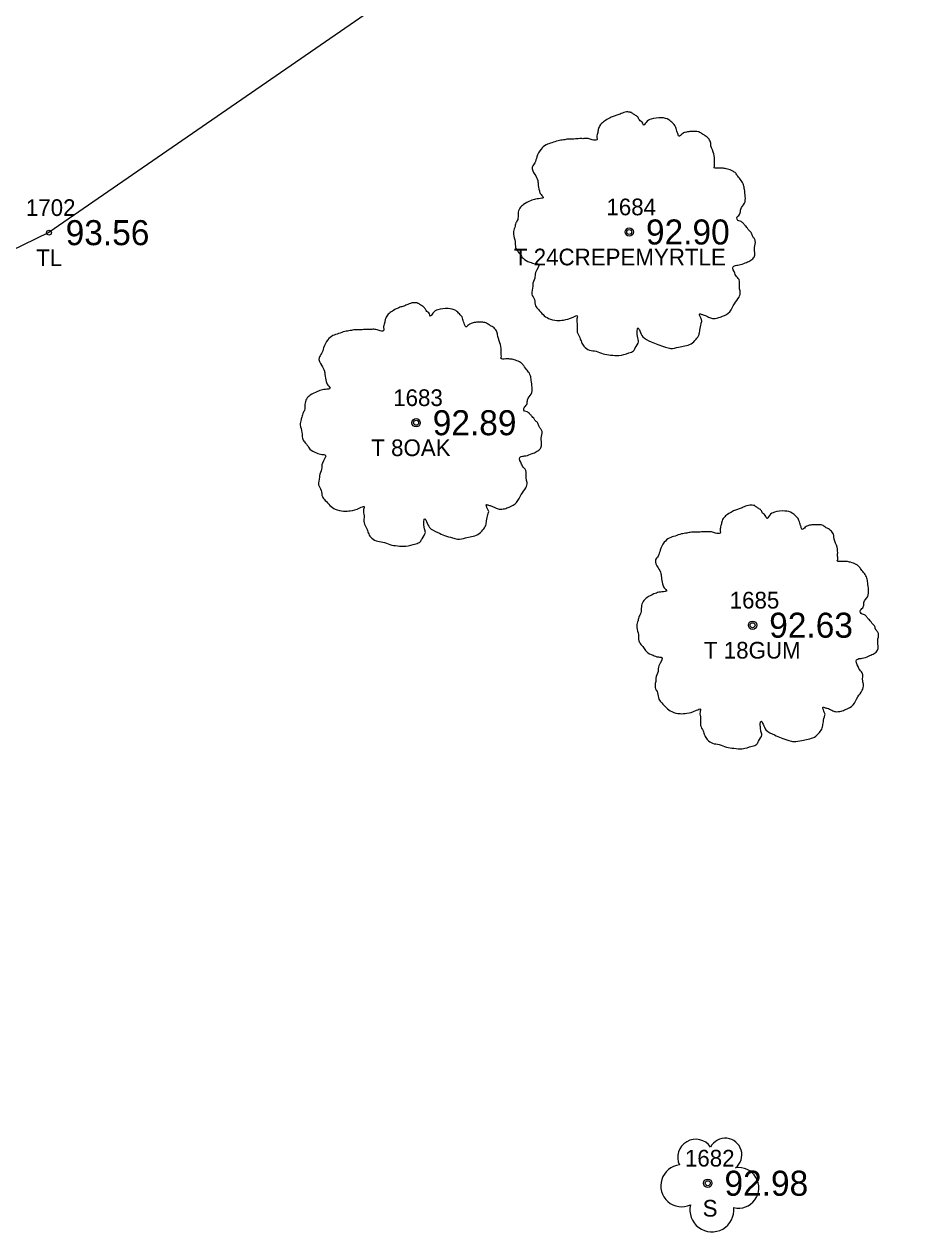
# Model space of a CAD drawing. Extents: x 2529517 to 2532038, y 935000 to 936944.
# Drawn here: x 2530911.6 to 2530965.7, y 935896 to 935968.4 of the extents above; entities that cross this region are included whole.
import ezdxf

# ---------------------------------------------------------------- set-up
doc = ezdxf.new("R2010")
doc.units = 0
for name, color, linetype in [('RD_EX_TX_VEG_ELEV', 7, 'Continuous'), ('RD_EX_VEG', 7, 'Continuous'), ('RD_EX_VEG_txCode', 7, 'Continuous'), ('RD_SMD_Locator', 7, 'Continuous')]:
    doc.layers.add(name, color=color, linetype=linetype)

msp = doc.modelspace()

# ---------------------------------------------------------------- linework, layer by layer
at = {"layer": 'RD_EX_VEG'}
msp.add_lwpolyline([(2531065.966, 935956.737), (2531029.723, 936036.27), (2530913.111, 935955.889), (2530857.851, 935929.004), (2530845.595, 935970.773)], dxfattribs=at)
for centre, radius in [((2530947.896, 935955.93), 0.25), ((2530947.884, 935955.911), 0.0001), ((2530935.115, 935944.498), 0.25), ((2530935.103, 935944.479), 0.0001), ((2530955.285, 935932.364), 0.25), ((2530955.273, 935932.346), 0.0001), ((2530952.603, 935898.92), 0.25)]:
    msp.add_circle(centre, radius, dxfattribs=at)
for centre, radius, start, end in [((2530951.882, 935900.468), 1.084, 34.97629, 204.75602), ((2530953.649, 935900.622), 0.995, 308.76261, 152.04674), ((2530951.04, 935898.765), 1.257, 96.45179, 294.73401), ((2530954.443, 935898.641), 1.218, 256.56668, 98.10463), ((2530952.849, 935897.324), 1.318, 166.88266, 5.75893)]:
    msp.add_arc(centre, radius, start, end, dxfattribs=at)
for points in [[(2530948.028, 935963.097), (2530947.728, 935963.122), (2530947.403, 935963.022), (2530947.153, 935962.923), (2530946.929, 935962.848), (2530946.704, 935962.748), (2530946.404, 935962.573), (2530946.179, 935962.373), (2530946.054, 935962.123), (2530946.004, 935961.898), (2530945.954, 935961.623), (2530945.954, 935961.448), (2530945.829, 935961.423), (2530945.679, 935961.448), (2530945.429, 935961.523), (2530945.179, 935961.523), (2530944.929, 935961.523), (2530944.58, 935961.498), (2530944.23, 935961.498), (2530943.955, 935961.448), (2530943.63, 935961.398), (2530943.255, 935961.273), (2530942.905, 935961.148), (2530942.605, 935960.898), (2530942.356, 935960.424), (2530942.231, 935960.074), (2530942.081, 935959.824), (2530942.231, 935959.374), (2530942.406, 935959.024), (2530942.43, 935958.824), (2530942.505, 935958.4), (2530942.605, 935958.175), (2530942.73, 935957.975), (2530942.655, 935957.95), (2530942.281, 935957.9), (2530941.981, 935957.8), (2530941.556, 935957.575), (2530941.331, 935957.35), (2530941.231, 935957.025), (2530941.206, 935956.675), (2530941.106, 935956.475), (2530941.031, 935956.2), (2530941.006, 935956.125), (2530940.956, 935955.801), (2530941.056, 935955.351), (2530941.081, 935955.001), (2530941.206, 935954.776), (2530941.356, 935954.601), (2530941.531, 935954.351), (2530941.931, 935954.126), (2530942.256, 935954.026), (2530942.455, 935954.001), (2530942.281, 935953.502), (2530942.231, 935953.152), (2530942.106, 935952.752), (2530942.106, 935952.677), (2530942.056, 935952.202), (2530942.206, 935951.877), (2530942.281, 935951.503), (2530942.455, 935951.278), (2530942.73, 935950.978), (2530943.055, 935950.753), (2530943.555, 935950.628), (2530943.955, 935950.653), (2530944.53, 935950.828), (2530944.779, 935950.903), (2530944.754, 935950.728), (2530944.779, 935950.353), (2530944.779, 935949.928), (2530944.929, 935949.603), (2530945.029, 935949.328), (2530945.179, 935949.079), (2530945.504, 935948.854), (2530945.904, 935948.779), (2530946.329, 935948.629), (2530946.779, 935948.554), (2530947.278, 935948.529), (2530947.878, 935948.679), (2530948.153, 935948.804), (2530948.253, 935948.979), (2530948.453, 935949.353), (2530948.403, 935949.578), (2530948.428, 935950.178), (2530948.528, 935950.003), (2530948.703, 935949.653), (2530949.203, 935949.353), (2530949.602, 935949.179), (2530950.077, 935949.029), (2530950.377, 935948.954), (2530950.852, 935949.029), (2530951.227, 935949.104), (2530951.601, 935949.229), (2530951.901, 935949.503), (2530952.076, 935949.778), (2530952.126, 935950.053), (2530952.201, 935950.428), (2530952.251, 935950.603)], [(2530952.251, 935950.603), (2530952.176, 935950.778), (2530952.126, 935951.028), (2530952.201, 935951.003), (2530952.376, 935950.953), (2530952.651, 935950.828), (2530952.876, 935950.753), (2530953.201, 935950.778), (2530953.476, 935950.878), (2530953.925, 935951.153), (2530954.2, 935951.627), (2530954.475, 935952.027), (2530954.55, 935952.352), (2530954.5, 935952.577), (2530954.475, 935953.077), (2530954.275, 935953.327), (2530954.225, 935953.452), (2530954.125, 935953.851), (2530954.2, 935953.901), (2530954.475, 935953.951), (2530954.85, 935954.076), (2530955.125, 935954.201), (2530955.35, 935954.376), (2530955.425, 935954.601), (2530955.4, 935955.001), (2530955.45, 935955.401), (2530955.375, 935955.551), (2530955.275, 935955.701), (2530955.2, 935955.901), (2530955.05, 935956.05), (2530954.95, 935956.2), (2530954.85, 935956.3), (2530954.725, 935956.45), (2530954.55, 935956.575), (2530954.4, 935956.625), (2530954.35, 935956.775), (2530954.5, 935956.975), (2530954.55, 935957.075), (2530954.575, 935957.3), (2530954.8, 935957.65), (2530954.85, 935958.05), (2530954.8, 935958.474), (2530954.75, 935958.749), (2530954.6, 935959.024), (2530954.4, 935959.274), (2530954.275, 935959.449), (2530954.1, 935959.574), (2530953.776, 935959.699), (2530953.526, 935959.749), (2530953.176, 935959.749), (2530952.976, 935959.799), (2530953.001, 935959.849), (2530953.001, 935959.999), (2530953.001, 935960.274), (2530952.926, 935960.723), (2530952.776, 935961.223), (2530952.776, 935961.248), (2530952.676, 935961.498), (2530952.451, 935961.698), (2530952.276, 935961.798), (2530952.076, 935961.923), (2530951.826, 935961.948), (2530951.527, 935961.948), (2530951.252, 935961.898), (2530951.052, 935961.798), (2530950.877, 935961.673), (2530950.802, 935961.823), (2530950.702, 935962.123), (2530950.652, 935962.273), (2530950.502, 935962.448), (2530950.277, 935962.648), (2530949.827, 935962.773), (2530949.203, 935962.698), (2530948.903, 935962.498), (2530948.753, 935962.323), (2530948.703, 935962.448), (2530948.503, 935962.648), (2530948.403, 935962.823), (2530948.228, 935962.948), (2530948.078, 935963.047), (2530947.978, 935963.097)], [(2530935.247, 935951.665), (2530934.947, 935951.69), (2530934.622, 935951.59), (2530934.373, 935951.49), (2530934.148, 935951.415), (2530933.923, 935951.315), (2530933.623, 935951.14), (2530933.398, 935950.94), (2530933.273, 935950.691), (2530933.223, 935950.466), (2530933.173, 935950.191), (2530933.173, 935950.016), (2530933.048, 935949.991), (2530932.898, 935950.016), (2530932.648, 935950.091), (2530932.398, 935950.091), (2530932.148, 935950.091), (2530931.799, 935950.066), (2530931.449, 935950.066), (2530931.174, 935950.016), (2530930.849, 935949.966), (2530930.474, 935949.841), (2530930.124, 935949.716), (2530929.825, 935949.466), (2530929.575, 935948.991), (2530929.45, 935948.641), (2530929.3, 935948.392), (2530929.45, 935947.942), (2530929.625, 935947.592), (2530929.65, 935947.392), (2530929.725, 935946.967), (2530929.825, 935946.742), (2530929.949, 935946.542), (2530929.875, 935946.517), (2530929.5, 935946.467), (2530929.2, 935946.367), (2530928.775, 935946.143), (2530928.55, 935945.918), (2530928.45, 935945.593), (2530928.425, 935945.243), (2530928.325, 935945.043), (2530928.25, 935944.768), (2530928.225, 935944.693), (2530928.175, 935944.368), (2530928.275, 935943.918), (2530928.3, 935943.569), (2530928.425, 935943.344), (2530928.575, 935943.169), (2530928.75, 935942.919), (2530929.15, 935942.694), (2530929.475, 935942.594), (2530929.675, 935942.569), (2530929.5, 935942.069), (2530929.45, 935941.719), (2530929.325, 935941.32), (2530929.325, 935941.245), (2530929.275, 935940.77), (2530929.425, 935940.445), (2530929.5, 935940.07), (2530929.675, 935939.845), (2530929.949, 935939.545), (2530930.274, 935939.321), (2530930.774, 935939.196), (2530931.174, 935939.221), (2530931.749, 935939.395), (2530931.999, 935939.47), (2530931.974, 935939.296), (2530931.999, 935938.921), (2530931.999, 935938.496), (2530932.148, 935938.171), (2530932.248, 935937.896), (2530932.398, 935937.646), (2530932.723, 935937.421), (2530933.123, 935937.346), (2530933.548, 935937.196), (2530933.998, 935937.121), (2530934.497, 935937.096), (2530935.097, 935937.246), (2530935.372, 935937.371), (2530935.472, 935937.546), (2530935.672, 935937.921), (2530935.622, 935938.146), (2530935.647, 935938.746), (2530935.747, 935938.571), (2530935.922, 935938.221), (2530936.422, 935937.921), (2530936.821, 935937.746), (2530937.296, 935937.596), (2530937.596, 935937.521), (2530938.071, 935937.596), (2530938.446, 935937.671), (2530938.821, 935937.796), (2530939.12, 935938.071), (2530939.295, 935938.346), (2530939.345, 935938.621), (2530939.42, 935938.996), (2530939.47, 935939.171)], [(2530939.47, 935939.171), (2530939.395, 935939.346), (2530939.345, 935939.595), (2530939.42, 935939.57), (2530939.595, 935939.52), (2530939.87, 935939.395), (2530940.095, 935939.321), (2530940.42, 935939.346), (2530940.695, 935939.445), (2530941.145, 935939.72), (2530941.419, 935940.195), (2530941.694, 935940.595), (2530941.769, 935940.92), (2530941.719, 935941.145), (2530941.694, 935941.644), (2530941.494, 935941.894), (2530941.444, 935942.019), (2530941.344, 935942.419), (2530941.419, 935942.469), (2530941.694, 935942.519), (2530942.069, 935942.644), (2530942.344, 935942.769), (2530942.569, 935942.944), (2530942.644, 935943.169), (2530942.619, 935943.569), (2530942.669, 935943.968), (2530942.594, 935944.118), (2530942.494, 935944.268), (2530942.419, 935944.468), (2530942.269, 935944.618), (2530942.169, 935944.768), (2530942.069, 935944.868), (2530941.944, 935945.018), (2530941.769, 935945.143), (2530941.619, 935945.193), (2530941.569, 935945.343), (2530941.719, 935945.543), (2530941.769, 935945.643), (2530941.794, 935945.868), (2530942.019, 935946.217), (2530942.069, 935946.617), (2530942.019, 935947.042), (2530941.969, 935947.317), (2530941.819, 935947.592), (2530941.619, 935947.842), (2530941.494, 935948.017), (2530941.319, 935948.142), (2530940.995, 935948.267), (2530940.745, 935948.317), (2530940.395, 935948.317), (2530940.195, 935948.367), (2530940.22, 935948.417), (2530940.22, 935948.566), (2530940.22, 935948.841), (2530940.145, 935949.291), (2530939.995, 935949.791), (2530939.995, 935949.816), (2530939.895, 935950.066), (2530939.67, 935950.266), (2530939.495, 935950.366), (2530939.295, 935950.491), (2530939.045, 935950.516), (2530938.746, 935950.516), (2530938.471, 935950.466), (2530938.271, 935950.366), (2530938.096, 935950.241), (2530938.021, 935950.391), (2530937.921, 935950.691), (2530937.871, 935950.84), (2530937.721, 935951.015), (2530937.496, 935951.215), (2530937.046, 935951.34), (2530936.422, 935951.265), (2530936.122, 935951.065), (2530935.972, 935950.89), (2530935.922, 935951.015), (2530935.722, 935951.215), (2530935.622, 935951.39), (2530935.447, 935951.515), (2530935.297, 935951.615), (2530935.197, 935951.665)], [(2530955.417, 935939.532), (2530955.117, 935939.557), (2530954.793, 935939.457), (2530954.543, 935939.357), (2530954.318, 935939.282), (2530954.093, 935939.182), (2530953.793, 935939.007), (2530953.568, 935938.807), (2530953.443, 935938.557), (2530953.393, 935938.332), (2530953.343, 935938.057), (2530953.343, 935937.882), (2530953.218, 935937.857), (2530953.068, 935937.882), (2530952.818, 935937.957), (2530952.569, 935937.957), (2530952.319, 935937.957), (2530951.969, 935937.932), (2530951.619, 935937.932), (2530951.344, 935937.882), (2530951.019, 935937.832), (2530950.644, 935937.707), (2530950.295, 935937.582), (2530949.995, 935937.333), (2530949.745, 935936.858), (2530949.62, 935936.508), (2530949.47, 935936.258), (2530949.62, 935935.808), (2530949.795, 935935.458), (2530949.82, 935935.258), (2530949.895, 935934.834), (2530949.995, 935934.609), (2530950.12, 935934.409), (2530950.045, 935934.384), (2530949.67, 935934.334), (2530949.37, 935934.234), (2530948.945, 935934.009), (2530948.72, 935933.784), (2530948.62, 935933.459), (2530948.595, 935933.109), (2530948.495, 935932.91), (2530948.42, 935932.635), (2530948.395, 935932.56), (2530948.345, 935932.235), (2530948.445, 935931.785), (2530948.47, 935931.435), (2530948.595, 935931.21), (2530948.745, 935931.035), (2530948.92, 935930.785), (2530949.32, 935930.561), (2530949.645, 935930.461), (2530949.845, 935930.436), (2530949.67, 935929.936), (2530949.62, 935929.586), (2530949.495, 935929.186), (2530949.495, 935929.111), (2530949.445, 935928.636), (2530949.595, 935928.311), (2530949.67, 935927.937), (2530949.845, 935927.712), (2530950.12, 935927.412), (2530950.444, 935927.187), (2530950.944, 935927.062), (2530951.344, 935927.087), (2530951.919, 935927.262), (2530952.169, 935927.337), (2530952.144, 935927.162), (2530952.169, 935926.787), (2530952.169, 935926.362), (2530952.319, 935926.038), (2530952.419, 935925.763), (2530952.569, 935925.513), (2530952.893, 935925.288), (2530953.293, 935925.213), (2530953.718, 935925.063), (2530954.168, 935924.988), (2530954.668, 935924.963), (2530955.267, 935925.113), (2530955.542, 935925.238), (2530955.642, 935925.413), (2530955.842, 935925.788), (2530955.792, 935926.013), (2530955.817, 935926.612), (2530955.917, 935926.437), (2530956.092, 935926.087), (2530956.592, 935925.788), (2530956.992, 935925.613), (2530957.466, 935925.463), (2530957.766, 935925.388), (2530958.241, 935925.463), (2530958.616, 935925.538), (2530958.991, 935925.663), (2530959.291, 935925.938), (2530959.466, 935926.212), (2530959.516, 935926.487), (2530959.59, 935926.862), (2530959.64, 935927.037)], [(2530959.64, 935927.037), (2530959.566, 935927.212), (2530959.516, 935927.462), (2530959.59, 935927.437), (2530959.765, 935927.387), (2530960.04, 935927.262), (2530960.265, 935927.187), (2530960.59, 935927.212), (2530960.865, 935927.312), (2530961.315, 935927.587), (2530961.59, 935928.062), (2530961.864, 935928.461), (2530961.939, 935928.786), (2530961.889, 935929.011), (2530961.864, 935929.511), (2530961.665, 935929.761), (2530961.615, 935929.886), (2530961.515, 935930.286), (2530961.59, 935930.336), (2530961.864, 935930.386), (2530962.239, 935930.511), (2530962.514, 935930.635), (2530962.739, 935930.81), (2530962.814, 935931.035), (2530962.789, 935931.435), (2530962.839, 935931.835), (2530962.764, 935931.985), (2530962.664, 935932.135), (2530962.589, 935932.335), (2530962.439, 935932.485), (2530962.339, 935932.635), (2530962.239, 935932.735), (2530962.114, 935932.885), (2530961.939, 935933.009), (2530961.79, 935933.059), (2530961.74, 935933.209), (2530961.889, 935933.409), (2530961.939, 935933.509), (2530961.964, 935933.734), (2530962.189, 935934.084), (2530962.239, 935934.484), (2530962.189, 935934.909), (2530962.139, 935935.184), (2530961.989, 935935.458), (2530961.79, 935935.708), (2530961.665, 935935.883), (2530961.49, 935936.008), (2530961.165, 935936.133), (2530960.915, 935936.183), (2530960.565, 935936.183), (2530960.365, 935936.233), (2530960.39, 935936.283), (2530960.39, 935936.433), (2530960.39, 935936.708), (2530960.315, 935937.158), (2530960.165, 935937.657), (2530960.165, 935937.682), (2530960.065, 935937.932), (2530959.84, 935938.132), (2530959.665, 935938.232), (2530959.466, 935938.357), (2530959.216, 935938.382), (2530958.916, 935938.382), (2530958.641, 935938.332), (2530958.441, 935938.232), (2530958.266, 935938.107), (2530958.191, 935938.257), (2530958.091, 935938.557), (2530958.041, 935938.707), (2530957.891, 935938.882), (2530957.666, 935939.082), (2530957.216, 935939.207), (2530956.592, 935939.132), (2530956.292, 935938.932), (2530956.142, 935938.757), (2530956.092, 935938.882), (2530955.892, 935939.082), (2530955.792, 935939.257), (2530955.617, 935939.382), (2530955.467, 935939.482), (2530955.367, 935939.532)]]:
    msp.add_spline(points, degree=3, dxfattribs=at)
at = {"layer": 'RD_SMD_Locator'}
for centre in [(2530913.111, 935955.889), (2530947.896, 935955.93), (2530935.115, 935944.498), (2530955.285, 935932.364), (2530952.603, 935898.92)]:
    msp.add_circle(centre, 0.15, dxfattribs=at)

# ---------------------------------------------------------------- texts
at = {"layer": 'RD_EX_TX_VEG_ELEV'}
for s, p in [('93.56', (2530914.111, 935955.139)), ('92.90', (2530948.896, 935955.18)), ('92.89', (2530936.115, 935943.748)), ('92.63', (2530956.285, 935931.614)), ('92.98', (2530953.603, 935898.17))]:
    msp.add_text(s, height=1.5, dxfattribs=at).set_placement(p)
at = {"layer": 'RD_EX_VEG_txCode'}
for s, p in [('1684', (2530946.526, 935956.93)), ('1702', (2530911.725, 935956.889)), ('TL', (2530912.339, 935953.889)), ('T 24CREPEMYRTLE', (2530940.979, 935953.93)), ('1683', (2530933.745, 935945.498)), ('T 8OAK', (2530932.43, 935942.498)), ('1685', (2530953.915, 935933.364)), ('T 18GUM', (2530952.372, 935930.364)), ('1682', (2530951.233, 935899.92)), ('S', (2530952.296, 935896.92))]:
    msp.add_text(s, height=1, dxfattribs=at).set_placement(p)

doc.saveas('drawing.dxf')
